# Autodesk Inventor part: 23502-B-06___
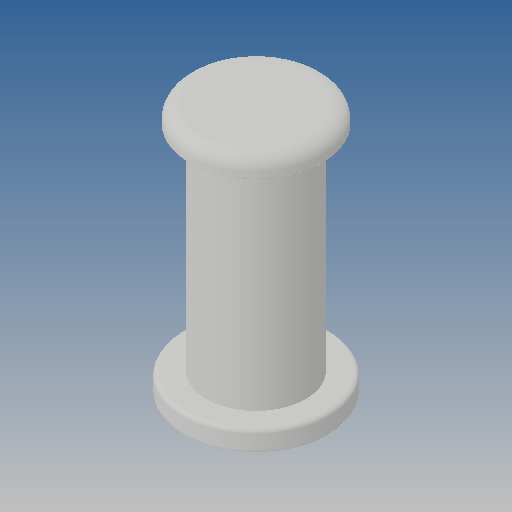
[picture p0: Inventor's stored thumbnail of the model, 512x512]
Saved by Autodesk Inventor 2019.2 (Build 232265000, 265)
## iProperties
Created: 2010-06
Part Number: 23502-B-06___
Material: Ogólny
Document SubType Name: Modeling
Designer: CADENGINEERING4
Density: 1 g/cm^3
Appearance: Domyślna
Author: CADENGINEERING4
Revision Number: ANY
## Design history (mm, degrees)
feature "NONE"
node "Bryła1"
